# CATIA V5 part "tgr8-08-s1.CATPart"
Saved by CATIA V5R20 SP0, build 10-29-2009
Part number: TGR8-08-S1
Revision: 2
Definition: design
Nomenclature: TGR8-08-S1
Source: made
Description: NOT SPECIFIED
Bounding box of the stored display mesh (mm): x -4 to 4, y -8 to 0, z -22 to 0.6
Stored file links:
  C:\Users\Raffaele\Desktop\3D X SITO CF\I-MOLD\TGR-S1\tgr8-s1.step\tgr8-08-s1.CATPart
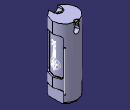
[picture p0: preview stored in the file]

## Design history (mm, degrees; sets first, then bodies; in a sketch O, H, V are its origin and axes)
Set1
  DatumCurve1 "COMPOSITE_CURVE #4316"
  DatumCurve2 "COMPOSITE_CURVE #4363"
  DatumCurve3 "COMPOSITE_CURVE #4596"
  DatumCurve4 "COMPOSITE_CURVE #4656"
  DatumCurve5 "COMPOSITE_CURVE #4708"
  DatumCurve6 "COMPOSITE_CURVE #4869"
  DatumCurve7 "COMPOSITE_CURVE #4896"
  DatumCurve8 "COMPOSITE_CURVE #4923"
  DatumCurve9 "COMPOSITE_CURVE #5009"
  DatumCurve10 "COMPOSITE_CURVE #5048"
  Line1 "LINE #5056": stored without definition
  DatumSurface1 "OPEN_SHELL #4143"
  DatumSurface2 "OPEN_SHELL #4240"
Body1 "MANIFOLD_SOLID_BREP #4241" (main body)
  Solid1: solid without history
